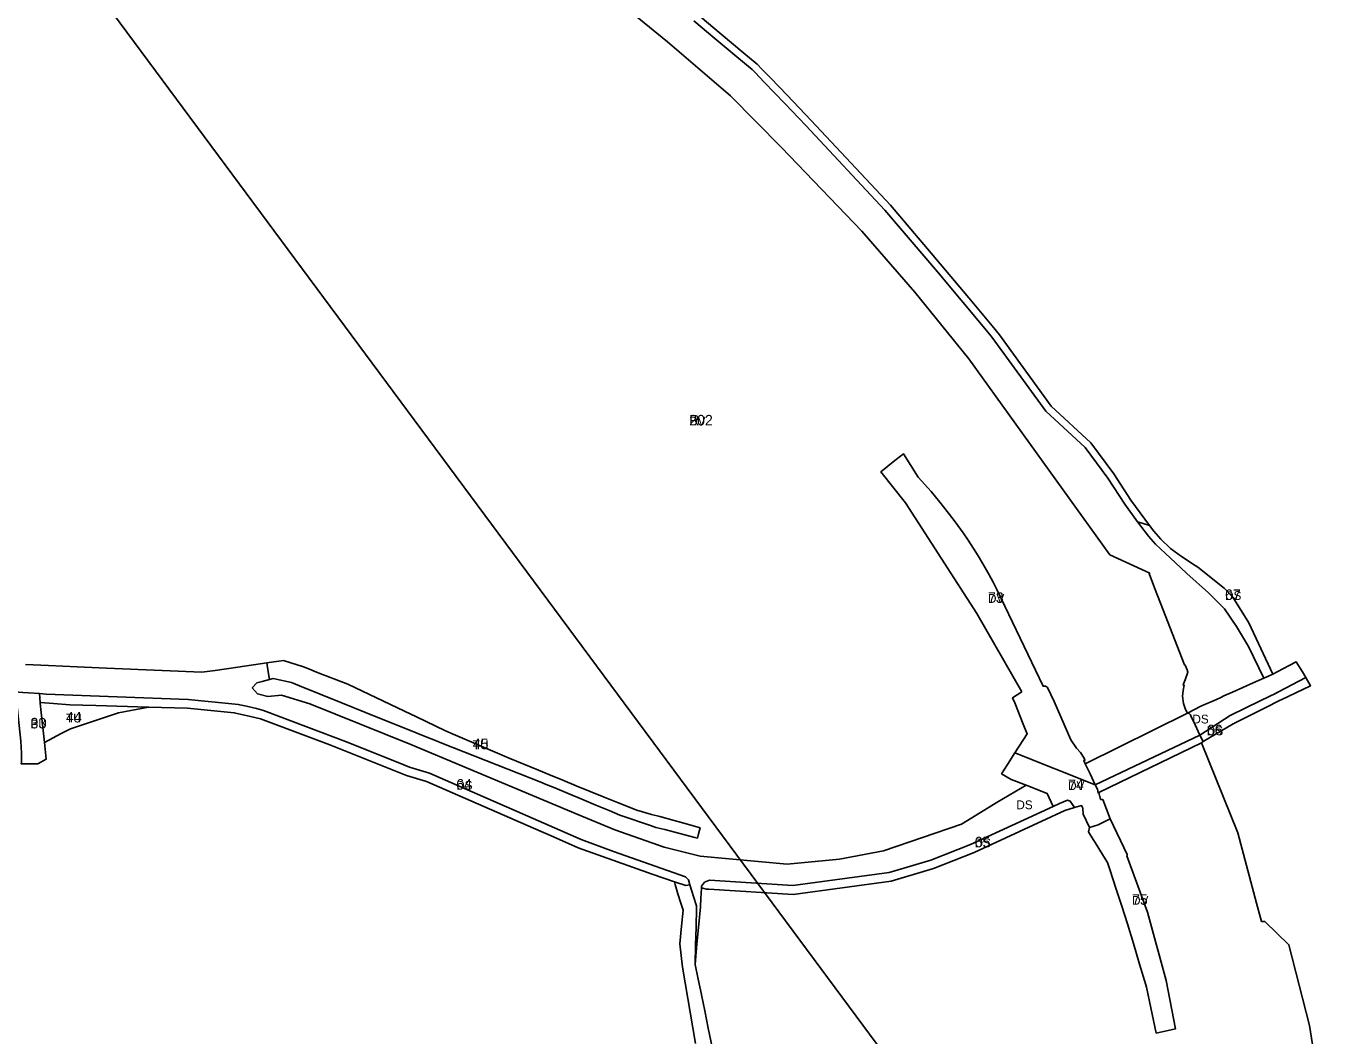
# Model space of a CAD drawing. Extents: x -535435 to -532834, y -1165802 to -1163866.
# Drawn here: x -533724 to -532979, y -1165015 to -1164441 of the extents above; entities that cross this region are included whole.
import ezdxf

# ---------------------------------------------------------------- set-up
doc = ezdxf.new("R2010")
doc.units = 0
for name, color, linetype in [('90320013', 7, 'Continuous'), ('90320023', 7, 'Continuous'), ('90350023', 7, 'Continuous'), ('90350033', 7, 'Continuous'), ('90380023', 7, 'Continuous'), ('90450023', 7, 'Continuous'), ('ID_navrh', 7, 'Continuous'), ('ID_rezerva', 7, 'Continuous'), ('ID_rezervaR', 7, 'Continuous')]:
    doc.layers.add(name, color=color, linetype=linetype)

msp = doc.modelspace()

# ---------------------------------------------------------------- linework, layer by layer
at = {"layer": '90320013'}
for points in [[(-533340.821, -1164435.131), (-533328.75, -1164445.191), (-533315.918, -1164455.886), (-533308.396, -1164462.16), (-533305.535, -1164465.123), (-533300.609, -1164470.229), (-533291.333, -1164479.846), (-533277.572, -1164494.141), (-533232.543, -1164542.376), (-533209.403, -1164569.613), (-533187.972, -1164595.15), (-533174.698, -1164611.056), (-533170.542, -1164616.153), (-533141.095, -1164656.677), (-533118.57, -1164677.495), (-533105.448, -1164695.285), (-533095.722, -1164710.135), (-533085.236, -1164724.572), (-533088.71, -1164723.46), (-533091.952, -1164722.472), (-533099.18, -1164712.521), (-533108.898, -1164697.684), (-533121.714, -1164680.309), (-533144.204, -1164659.543), (-533174.61, -1164617.7), (-533177.92, -1164613.75), (-533205.86, -1164580.27), (-533235.68, -1164545.17), (-533280.62, -1164497.03), (-533292.65, -1164484.53), (-533304.36, -1164472.39), (-533309.57, -1164466.99), (-533311.26, -1164465.24), (-533320, -1164457.95), (-533332.48, -1164447.55), (-533344.43, -1164437.59)], [(-533724.542, -1164803.644), (-533711.44, -1164804.22), (-533695.1, -1164804.93), (-533678.4, -1164805.66), (-533646.8, -1164807.03), (-533624.24, -1164808.01), (-533616.74, -1164806.99), (-533603.81, -1164805.24), (-533587.26, -1164802.74), (-533586.49, -1164807.8), (-533585.817, -1164812.22), (-533589.91, -1164813.28), (-533592.91, -1164814.08), (-533595.59, -1164816.83), (-533592.59, -1164820.3), (-533586.7, -1164821.82), (-533578.89, -1164821.11), (-533562.74, -1164826), (-533505.42, -1164849.16), (-533410.4, -1164889.02), (-533389.23, -1164897.67), (-533361.33, -1164907.54), (-533340.78, -1164912.67), (-533291.28, -1164917.31), (-533261.61, -1164914.36), (-533236.41, -1164909.7), (-533192.2, -1164894.47), (-533171.4, -1164881.68), (-533155.355, -1164872.361), (-533143.352, -1164877.01), (-533139.96, -1164884.348), (-533186.91, -1164906.05), (-533209.62, -1164915), (-533233.2, -1164922.05), (-533287.97, -1164929.42), (-533335.37, -1164926.38), (-533338.28, -1164927.4), (-533340.037, -1164929.741), (-533340.076, -1164930.725), (-533340.209, -1164934.096), (-533340.301, -1164936.333), (-533340.51, -1164941.413), (-533341.509, -1164951.373), (-533342.636, -1164962.604), (-533343.59, -1164974.269), (-533343.339, -1164963.273), (-533343.105, -1164953.029), (-533342.858, -1164942.21), (-533342.83, -1164941), (-533344.519, -1164935.65), (-533345.48, -1164932.608), (-533346.61, -1164929.03), (-533347.36, -1164926.15), (-533349.13, -1164924.37), (-533390.15, -1164909.93), (-533408.38, -1164903.25), (-533494.69, -1164865.48), (-533506.09, -1164862.02), (-533509.4, -1164860.71), (-533541, -1164847.96), (-533589.21, -1164829.81), (-533593.06, -1164828.7), (-533598.9, -1164827.3), (-533603.51, -1164826.37), (-533605.27, -1164826.14), (-533632.04, -1164823.51), (-533712.82, -1164820.51), (-533716.647, -1164820.234), (-533722.741, -1164819.796), (-533726.02, -1164819.56)]]:
    msp.add_lwpolyline(points, dxfattribs=at)
msp.add_lwpolyline([(-533121.79, -1164860.11), (-533063.56, -1164831.41), (-533055.93, -1164827.39), (-533047.16, -1164823.47), (-533044.65, -1164822.35), (-533042.84, -1164821.55), (-533037.94, -1164819.35), (-533026.23, -1164814.12), (-533020.215, -1164811.436), (-533017.474, -1164810.213), (-533014.98, -1164809.1), (-533009.419, -1164806.211), (-533001.68, -1164802.19), (-532998.25, -1164807.9), (-532996.306, -1164811.14), (-533011.715, -1164819.211), (-533013.133, -1164819.954), (-533021.837, -1164824.165), (-533039.27, -1164832.6), (-533056.49, -1164843.86), (-533116.02, -1164872.19), (-533119.01, -1164865.81)], close=True, dxfattribs=at)
at = {"layer": '90320023'}
for points in [[(-533070.523, -1164745.61), (-533076.175, -1164740.567), (-533081.802, -1164735.237), (-533085.762, -1164730.682), (-533090.161, -1164724.938), (-533091.952, -1164722.472), (-533088.71, -1164723.46), (-533085.236, -1164724.572), (-533082.733, -1164727.765), (-533078.797, -1164732.292), (-533073.191, -1164737.593), (-533067.062, -1164742.2), (-533059.292, -1164747.31), (-533057.72, -1164748.344), (-533042.687, -1164760.287), (-533037.824, -1164765.421), (-533028.64, -1164779.86), (-533014.98, -1164809.1), (-533020.215, -1164811.436), (-533028.941, -1164793.371), (-533035.714, -1164782.121), (-533042.43, -1164772.055), (-533051.594, -1164762.938), (-533063.86, -1164751.81)], [(-533012.897, -1164819.83), (-533011.715, -1164819.211), (-532996.306, -1164811.14), (-532993.57, -1164815.7), (-533010.27, -1164823.69), (-533010.95, -1164824.01), (-533019.402, -1164828.244), (-533036.803, -1164836.961), (-533037.447, -1164837.342), (-533037.682, -1164837.481), (-533054.66, -1164847.53), (-533055.68, -1164848.17), (-533113.94, -1164876.55), (-533114.4, -1164876.67), (-533114.81, -1164874.57), (-533116.02, -1164872.19), (-533056.49, -1164843.86), (-533039.27, -1164832.6), (-533021.837, -1164824.165), (-533013.133, -1164819.954)], [(-533425.87, -1164900.96), (-533431.14, -1164898.61), (-533496.424, -1164870.179), (-533507.739, -1164866.745), (-533551.367, -1164849.4), (-533590.786, -1164834.559), (-533596.46, -1164833.25), (-533605.839, -1164831.108), (-533632.378, -1164828.501), (-533654.486, -1164827.886), (-533684.543, -1164827.049), (-533699.25, -1164826.64), (-533708.69, -1164825.86), (-533716.135, -1164825.246), (-533716.647, -1164820.234), (-533712.82, -1164820.51), (-533632.04, -1164823.51), (-533605.27, -1164826.14), (-533603.51, -1164826.37), (-533598.9, -1164827.3), (-533593.06, -1164828.7), (-533589.21, -1164829.81), (-533541, -1164847.96), (-533509.4, -1164860.71), (-533506.09, -1164862.02), (-533494.69, -1164865.48), (-533408.38, -1164903.25), (-533390.15, -1164909.93), (-533349.13, -1164924.37), (-533347.36, -1164926.15), (-533346.61, -1164929.03), (-533349.014, -1164929.428), (-533355.407, -1164927.219), (-533368.121, -1164922.828), (-533410.244, -1164907.892)], [(-533127.88, -1164885.08), (-533133.323, -1164886.788), (-533184.943, -1164910.649), (-533207.984, -1164919.73), (-533232.144, -1164926.953), (-533287.795, -1164934.442), (-533335.892, -1164931.357), (-533337.2, -1164931.49), (-533340.076, -1164930.725), (-533340.037, -1164929.741), (-533338.28, -1164927.4), (-533335.37, -1164926.38), (-533287.97, -1164929.42), (-533233.2, -1164922.05), (-533209.62, -1164915), (-533186.91, -1164906.05), (-533139.96, -1164884.348), (-533136.46, -1164882.73), (-533131.844, -1164880.814), (-533130.27, -1164881.37)]]:
    msp.add_lwpolyline(points, close=True, dxfattribs=at)
at = {"layer": '90350023'}
for points in [[(-533157.83, -1164819.27), (-533183.34, -1164774.65), (-533224.07, -1164711.63), (-533238.085, -1164694.066), (-533230.072, -1164687.654), (-533225.204, -1164683.758), (-533216.777, -1164697.165), (-533209.409, -1164705.307), (-533204.377, -1164711.27), (-533199.44, -1164717.478), (-533195.682, -1164722.466), (-533191.148, -1164728.822), (-533188.351, -1164732.944), (-533185.298, -1164737.639), (-533182.674, -1164741.852), (-533179.464, -1164747.253), (-533176.389, -1164752.709), (-533174.141, -1164756.895), (-533171.85, -1164761.354), (-533145.683, -1164816.04), (-533145.227, -1164815.953), (-533144.641, -1164815.909), (-533144.251, -1164815.953), (-533143.6, -1164816.322), (-533143.209, -1164816.81), (-533139.39, -1164824.708), (-533129.85, -1164846.49), (-533126.75, -1164851.21), (-533124.52, -1164853.64), (-533122.39, -1164856.98), (-533121.94, -1164858.07), (-533122.6, -1164858.35), (-533121.79, -1164860.11), (-533119.01, -1164865.81), (-533116.02, -1164872.19), (-533161.703, -1164853.84), (-533154.75, -1164843.06), (-533154.89, -1164842.74), (-533156.99, -1164837.52), (-533158.74, -1164833.17), (-533161.85, -1164825.47), (-533163.04, -1164822.52)], [(-533128.683, -1164883.833), (-533130.27, -1164881.37), (-533131.844, -1164880.814), (-533136.46, -1164882.73), (-533139.96, -1164884.348), (-533143.352, -1164877.01), (-533155.355, -1164872.361), (-533163.824, -1164869.081), (-533169.319, -1164865.777), (-533166.05, -1164860.58), (-533161.703, -1164853.84), (-533116.02, -1164872.19), (-533114.81, -1164874.57), (-533114.4, -1164876.67), (-533113.94, -1164876.55), (-533113, -1164880.39), (-533111.8, -1164880.45), (-533107.544, -1164891.527), (-533114.4, -1164894.79), (-533119.37, -1164896.37), (-533122.912, -1164888.766), (-533123.175, -1164885.463), (-533123.831, -1164883.862), (-533127.88, -1164885.08)], [(-533114.4, -1164894.79), (-533107.544, -1164891.527), (-533097.918, -1164911.73), (-533097.896, -1164912.121), (-533098.11, -1164912.42), (-533086.39, -1164944.59), (-533075.69, -1164983.34), (-533070.375, -1165010.82), (-533081.32, -1165013.31), (-533084.4, -1164998.97), (-533086.92, -1164987.26), (-533087.36, -1164985.79), (-533090.86, -1164974.13), (-533094.38, -1164962.37), (-533097.74, -1164951.15), (-533100.95, -1164941.1), (-533104.27, -1164930.9), (-533107.52, -1164920.92), (-533109.04, -1164916.24), (-533111.26, -1164912.65), (-533116.11, -1164904.82), (-533117.14, -1164903.15), (-533119.82, -1164898.82), (-533119.37, -1164896.37)]]:
    msp.add_lwpolyline(points, close=True, dxfattribs=at)
at = {"layer": '90350033'}
for points in [[(-533200.383, -1165073.214), (-533682.598, -1164422.461)], [(-533393.01, -1164421.73), (-533359.31, -1164449.39), (-533323.6, -1164480.19), (-533294.45, -1164509.67), (-533248.86, -1164557.23), (-533218.62, -1164591.93), (-533187.88, -1164629.82), (-533107.67, -1164741.3), (-533085.07, -1164751.78), (-533085.42, -1164751.91), (-533082.39, -1164760.04), (-533078.96, -1164768.7), (-533065.26, -1164803.77), (-533064.85, -1164804.08), (-533063.85, -1164806.75), (-533063.41, -1164808.03), (-533064.98, -1164812.34), (-533066.05, -1164815.28), (-533065.52, -1164815.47), (-533066.12, -1164818.42), (-533066.32, -1164821.75), (-533065.88, -1164825.93), (-533064.62, -1164829.31), (-533063.56, -1164831.41), (-533063.04, -1164831.41), (-533062.61, -1164831.54), (-533062.18, -1164831.87), (-533061.94, -1164832.22), (-533061.6, -1164832.94), (-533059.24, -1164838), (-533056.49, -1164843.86), (-533054.66, -1164847.53), (-533055.68, -1164848.17), (-533035.02, -1164899.39), (-533024.33, -1164939.46), (-533021.57, -1164949.83), (-533019.65, -1164949.83), (-533005.91, -1164963.1), (-532994.2, -1165009.04), (-532979.21, -1165103.79)]]:
    msp.add_lwpolyline(points, dxfattribs=at)
at = {"layer": '90380023'}
for points in [[(-533541.19, -1164814.8), (-533508.929, -1164830.209), (-533502.187, -1164833.429), (-533485.98, -1164841.17), (-533482.547, -1164842.741), (-533449.329, -1164857.017), (-533432.806, -1164863.822), (-533426.826, -1164866.284), (-533418.937, -1164869.534), (-533411.249, -1164872.7), (-533403.421, -1164875.924), (-533395.416, -1164879.165), (-533387.877, -1164882.185), (-533376.769, -1164886.588), (-533368.48, -1164888.881), (-533363.81, -1164890.174), (-533355.604, -1164892.445), (-533347.953, -1164894.562), (-533340.838, -1164896.53), (-533341.727, -1164900.001), (-533342.327, -1164902.343), (-533343.76, -1164901.98), (-533353.15, -1164899.58), (-533360.93, -1164897.6), (-533365.96, -1164896.32), (-533369.05, -1164895.26), (-533373.49, -1164893.74), (-533381.38, -1164891.04), (-533386.52, -1164889.28), (-533392.63, -1164886.74), (-533400.11, -1164883.63), (-533408.04, -1164880.32), (-533415.86, -1164877.07), (-533423.51, -1164873.88), (-533428.43, -1164871.84), (-533431.47, -1164870.62), (-533487.68, -1164848.33), (-533491.23, -1164846.91), (-533497.24, -1164844.53), (-533502.39, -1164842.48), (-533531.09, -1164830.9), (-533545.15, -1164825.22), (-533568.75, -1164815.7), (-533573.32, -1164813.85), (-533583.58, -1164811.64), (-533585.817, -1164812.22), (-533586.49, -1164807.8), (-533587.26, -1164802.74), (-533577.82, -1164801.33), (-533566.47, -1164805.04), (-533563.91, -1164806.02), (-533557.97, -1164808.32)], [(-533700.79, -1164841.16), (-533704.29, -1164842.98), (-533713.818, -1164847.949), (-533715.547, -1164831.013), (-533716.102, -1164825.575), (-533716.135, -1164825.246), (-533708.69, -1164825.86), (-533699.25, -1164826.64), (-533684.543, -1164827.049), (-533654.486, -1164827.886), (-533671.59, -1164831.22), (-533699.02, -1164840.23)]]:
    msp.add_lwpolyline(points, close=True, dxfattribs=at)
msp.add_lwpolyline([(-533343.416, -1165019.324), (-533350.73, -1164975.81), (-533352.303, -1164962.6), (-533351.343, -1164952.464), (-533350.481, -1164943.362), (-533351.34, -1164940.58), (-533351.86, -1164939.38), (-533353.414, -1164934.051), (-533354.932, -1164928.848), (-533355.407, -1164927.219), (-533349.014, -1164929.428), (-533346.61, -1164929.03), (-533345.48, -1164932.608), (-533344.519, -1164935.65), (-533342.83, -1164941), (-533342.858, -1164942.21), (-533343.105, -1164953.029), (-533343.339, -1164963.273), (-533343.59, -1164974.269), (-533341.865, -1164982.699), (-533340.094, -1164991.354), (-533340.069, -1164991.475), (-533338.183, -1165000.693), (-533336.164, -1165010.56), (-533333.91, -1165021.36)], dxfattribs=at)
at = {"layer": '90450023'}
msp.add_lwpolyline([(-533730.54, -1164819.23), (-533726.02, -1164819.56), (-533722.741, -1164819.796), (-533716.647, -1164820.234), (-533716.135, -1164825.246), (-533716.102, -1164825.575), (-533715.547, -1164831.013), (-533713.818, -1164847.949), (-533712.834, -1164857.586), (-533717.48, -1164860.13), (-533724, -1164860.16), (-533726.94, -1164860.18), (-533726.73, -1164859.25), (-533726.9, -1164854), (-533727.12, -1164847.21), (-533729.7, -1164824.13), (-533730.04, -1164821.1)], close=True, dxfattribs=at)

# ---------------------------------------------------------------- texts
at = {"layer": '90320013'}
for p in [(-533060.7883, -1164837.19), (-533160.9124, -1164885.9645)]:
    msp.add_text('DS', height=5, rotation=360, dxfattribs=at).set_placement(p)
at = {"layer": '90320023'}
for rotation, p in [(359.9999999, (-533042.2031, -1164766.954)), (0, (-533052.56, -1164843.905)), (0, (-533479.5318, -1164874.831)), (360, (-533184.6608, -1164907.628))]:
    msp.add_text('DS', height=5, rotation=rotation, dxfattribs=at).set_placement(p)
at = {"layer": '90350023'}
for rotation, p in [(0.0000001, (-533177.0525, -1164768.5897)), (0.0000001, (-533131.488, -1164875.105)), (0, (-533095.0975, -1164940.3315))]:
    msp.add_text('DV', height=5, rotation=rotation, dxfattribs=at).set_placement(p)
at = {"layer": '90350033'}
msp.add_text('DV', height=5, rotation=359.9999999, dxfattribs=at).set_placement((-533346.9885, -1164667.693))
at = {"layer": '90380023'}
for rotation, p in [(0, (-533701.4691, -1164836.5975)), (360, (-533470.1103, -1164851.8365))]:
    msp.add_text('TU', height=5, rotation=rotation, dxfattribs=at).set_placement(p)
at = {"layer": '90450023'}
msp.add_text('PU', height=5, rotation=360, dxfattribs=at).set_placement((-533721.687, -1164840.0106))
at = {"layer": 'ID_navrh'}
for s, rotation, p in [('73', 0, (-533177.0525, -1164768.5897)), ('67', 360, (-533042.2031, -1164766.954)), ('44', 0, (-533701.4691, -1164836.5975)), ('33', 360, (-533721.687, -1164840.0106)), ('66', 0, (-533052.56, -1164843.905)), ('45', 0, (-533470.1103, -1164851.8365)), ('64', 0.0000001, (-533479.5318, -1164874.831)), ('74', 0, (-533131.488, -1164875.105)), ('65', 360, (-533184.6608, -1164907.628)), ('75', 360, (-533095.0975, -1164940.3315))]:
    msp.add_text(s, height=6, rotation=rotation, dxfattribs=at).set_placement(p)
at = {"layer": 'ID_rezerva'}
msp.add_text('202', height=6, rotation=360, dxfattribs=at).set_placement((-533346.9885, -1164667.693))
at = {"layer": 'ID_rezervaR'}
msp.add_text('R', height=6, rotation=360, dxfattribs=at).set_placement((-533346.9885, -1164667.693))

doc.saveas('drawing.dxf')
